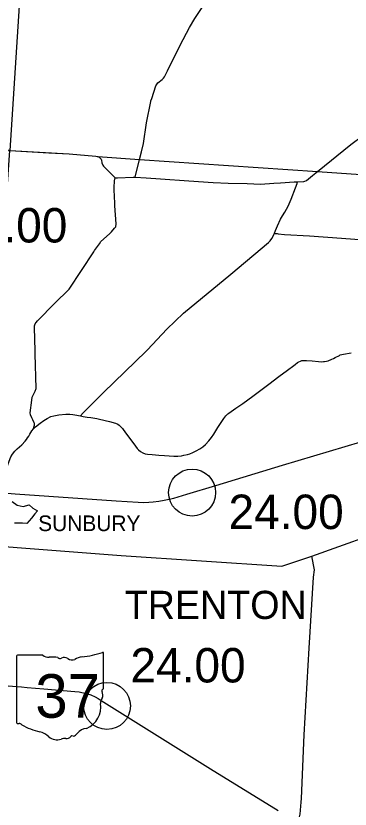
# Model space of a CAD drawing. Extents: x 1597222 to 1925846, y 496284 to 911751.
# Drawn here: x 1872161 to 1882846, y 810051 to 835395 of the extents above; entities that cross this region are included whole.
import ezdxf

# ---------------------------------------------------------------- set-up
doc = ezdxf.new("R2010")
doc.units = 0
for name, color, linetype in [('Default', 7, 'Continuous'), ('GM_X_Corporation', 7, 'Continuous'), ('GM_X_Corporation_Text', 7, 'Continuous'), ('GM_X_County_Road', 7, 'Continuous'), ('GM_X_State_Route', 7, 'Continuous'), ('GM_X_State_Shield', 7, 'Continuous'), ('GM_X_Township', 7, 'Continuous'), ('GM_X_Township_Road', 7, 'Continuous'), ('GM_X_Township_Text', 7, 'Continuous'), ('GM_X_US_Route', 7, 'Continuous')]:
    doc.layers.add(name, color=color, linetype=linetype)

msp = doc.modelspace()

# ---------------------------------------------------------------- linework, layer by layer
at = {"layer": 'Default'}
for centre in [(1877795, 820165), (1875074, 813348)]:
    msp.add_circle(centre, 750, dxfattribs=at)
at = {"layer": 'GM_X_Corporation'}
msp.add_lwpolyline([(1872043, 819876), (1872199, 819766), (1872392, 819723), (1872582, 819770), (1872706, 819663), (1872848, 819582), (1872764, 819484), (1872661, 819350), (1872513, 819172), (1872369, 819183), (1872118, 819190)], dxfattribs=at)
at = {"layer": 'GM_X_County_Road'}
for points in [[(1881648, 830290), (1881808, 830417), (1882869, 831288), (1883240, 831567)], [(1874227, 822615), (1874317, 822710), (1874959, 823358), (1876327, 824682), (1876365, 824720), (1876987, 825381), (1877524, 825893), (1879029, 827144), (1880240, 828159), (1880290, 828209), (1880342, 828279), (1880387, 828358), (1880432, 828452), (1880464, 828542), (1880520, 828684), (1880625, 828898), (1880689, 829004), (1880756, 829118), (1880864, 829316), (1880962, 829539), (1881103, 829903), (1881150, 830037), (1881159, 830094), (1881361, 830106), (1881400, 830115), (1881455, 830137), (1881648, 830290)], [(1872724, 822198), (1872792, 822267), (1872943, 822383), (1873056, 822467), (1873160, 822533), (1873276, 822590), (1873373, 822621), (1873532, 822646), (1873759, 822667), (1873891, 822665), (1873977, 822657), (1874044, 822647), (1874227, 822615), (1874315, 822599), (1874444, 822579), (1874557, 822560), (1874752, 822527), (1874836, 822512), (1875152, 822435), (1875346, 822380), (1875416, 822349), (1875458, 822321), (1875497, 822287), (1875565, 822207), (1875667, 822073), (1875831, 821849), (1875981, 821648), (1876039, 821575), (1876079, 821533), (1876143, 821482), (1876217, 821438), (1876297, 821406), (1876374, 821389), (1876519, 821376), (1876727, 821364), (1876913, 821349), (1877214, 821328), (1877336, 821330), (1877454, 821342), (1877534, 821356), (1877649, 821382), (1877722, 821406), (1877821, 821445), (1877928, 821496), (1878043, 821558), (1878138, 821626), (1878219, 821701), (1878331, 821818), (1878413, 821920), (1878486, 822032), (1878616, 822239), (1878743, 822436), (1878811, 822535), (1878842, 822578), (1878871, 822613), (1878895, 822642), (1878934, 822678), (1878967, 822704), (1879044, 822758), (1879197, 822860), (1879414, 823008), (1879735, 823245), (1879901, 823370), (1880245, 823625), (1880570, 823871), (1880847, 824079), (1881042, 824227), (1881087, 824259), (1881166, 824319), (1881210, 824345), (1881256, 824365), (1881305, 824380), (1881378, 824389), (1881448, 824388), (1881628, 824373), (1881838, 824352), (1881925, 824346), (1881993, 824349), (1882027, 824352), (1882091, 824364), (1882142, 824378), (1882259, 824424), (1882312, 824450), (1882368, 824481), (1882502, 824549), (1882531, 824563), (1882576, 824578), (1882637, 824590), (1882881, 824632)], [(1871742, 820151), (1871742, 820151), (1871754, 820333), (1871771, 820532), (1871780, 820600), (1871796, 820672), (1871893, 821017), (1871942, 821170), (1871996, 821311), (1872051, 821390), (1872132, 821486), (1872206, 821558), (1872281, 821630), (1872352, 821694), (1872457, 821804), (1872502, 821861), (1872537, 821910), (1872571, 821965), (1872610, 822031), (1872673, 822132), (1872724, 822198)], [(1871277, 818480), (1872206, 818406), (1875525, 818156), (1880663, 817814), (1881619, 818131), (1884362, 819111), (1887858, 818871), (1889457, 818761), (1891623, 818604), (1892346, 818560), (1895326, 818344), (1897532, 818224), (1897769, 818211), (1897801, 818204), (1897822, 818179)]]:
    msp.add_lwpolyline(points, dxfattribs=at)
at = {"layer": 'GM_X_State_Route'}
msp.add_lwpolyline([(1871455, 814026), (1871491, 814021), (1871569, 814014), (1871759, 814000), (1871910, 813989), (1872340, 813955), (1872527, 813939), (1873053, 813896), (1874044, 813812), (1874182, 813797), (1874274, 813782), (1874381, 813759), (1874562, 813699), (1874700, 813634), (1874793, 813581), (1874892, 813523), (1878383, 811338), (1880549, 810005)], dxfattribs=at)
at = {"layer": 'GM_X_State_Shield'}
for p, q in [((1872182, 814935), (1872182, 812822)), ((1872182, 814935), (1872182, 812822)), ((1873024, 814972), (1872209, 814972)), ((1873024, 814972), (1872209, 814972)), ((1874966, 813919), (1874966, 815024)), ((1874966, 813919), (1874966, 815024)), ((1874966, 813919), (1874966, 813919)), ((1874966, 813919), (1874966, 813919))]:
    msp.add_line(p, q, dxfattribs=at)
for centre, radius, start, end in [((1873974, 817853), 2953, 275.8445, 288.9065), ((1873974, 817853), 2953, 275.8445, 288.9065), ((1874935, 815029), 31, 351.8621, 97.738), ((1874935, 815029), 31, 351.8621, 97.738), ((1872213, 814940), 32.3, 98.1301, 188.1301), ((1872213, 814940), 32.3, 98.1301, 188.1301), ((1873219, 815217), 313, 231.6195, 271.1119), ((1873219, 815217), 313, 231.6195, 271.1119), ((1873322, 813785), 1123, 80.4867, 94.9883), ((1873322, 813785), 1123, 80.4867, 94.9883), ((1873577, 814951), 90.3, 219.7921, 297.1024), ((1873577, 814951), 90.3, 219.7921, 297.1024), ((1873710, 814707), 188, 54.4667, 119.1411), ((1873710, 814707), 188, 54.4667, 119.1411), ((1873952, 815042), 226, 233.8562, 294.8282), ((1873952, 815042), 226, 233.8562, 294.8282), ((1874351, 814326), 594, 97.3462, 120.7689), ((1874351, 814326), 594, 97.3462, 120.7689), ((1874959, 813838), 48, 107.944, 210.337), ((1874959, 813838), 48, 107.944, 210.337), ((1874654, 813698), 288, 340.033, 23.6496), ((1874654, 813698), 288, 340.033, 23.6496), ((1874933, 813914), 33.2, 289.6038, 7.7341), ((1874933, 813914), 33.2, 289.6038, 7.7341), ((1875077, 813456), 210, 136.8065, 186.9296), ((1875077, 813456), 210, 136.8065, 186.9296), ((1874139, 813315), 739, 292.3089, 8.9858), ((1874139, 813315), 739, 292.3089, 8.9858), ((1872214, 812818), 32.5, 171.9584, 258.3066), ((1872214, 812818), 32.5, 171.9584, 258.3066), ((1872219, 813034), 248, 267.339, 280.6039), ((1872219, 813034), 248, 267.339, 280.6039), ((1872269, 812700), 89.5, 29.7484, 93.2717), ((1872269, 812700), 89.5, 29.7484, 93.2717), ((1873400, 814599), 2132, 240.4129, 257.1985), ((1873400, 814599), 2132, 240.4129, 257.1985), ((1872764, 811873), 667, 47.1842, 75.836), ((1872764, 811873), 667, 47.1842, 75.836), ((1874451, 812229), 404, 94.4031, 142.5768), ((1874451, 812229), 404, 94.4031, 142.5768), ((1873486, 812690), 423, 230.7004, 286.2918), ((1873486, 812690), 423, 230.7004, 286.2918), ((1873731, 811959), 348, 85.6951, 111.2099), ((1873731, 811959), 348, 85.6951, 111.2099), ((1873761, 812531), 226, 268.777, 315.5493), ((1873761, 812531), 226, 268.777, 315.5493), ((1873965, 812327), 63.5, 65.7517, 132.6484), ((1873965, 812327), 63.5, 65.7517, 132.6484), ((1873938, 812617), 239, 282.8732, 323.2771), ((1873938, 812617), 239, 282.8732, 323.2771)]:
    msp.add_arc(centre, radius, start, end, dxfattribs=at)
at = {"layer": 'GM_X_Township'}
for points in [[(1850615, 859080), (1861827, 858324), (1863977, 858188), (1869100, 857855), (1873671, 857558), (1873447, 853777), (1873266, 851105), (1872889, 845433), (1872874, 845201), (1872678, 842151), (1872497, 839344), (1872306, 836385), (1871965, 831096), (1871301, 831135), (1870943, 831158), (1868637, 831266), (1861106, 831707), (1859467, 831803), (1858606, 831851), (1854821, 832136)], [(1870309, 808163), (1870779, 814239), (1870903, 816053), (1870933, 816495), (1870943, 816996), (1871003, 817857), (1871065, 818497), (1871124, 819057), (1871199, 820179), (1871965, 831096), (1873866, 830983), (1874715, 830911), (1874782, 830900), (1876113, 830808), (1881808, 830417), (1885186, 830186), (1888609, 830001), (1895732, 829600), (1898513, 829466)]]:
    msp.add_lwpolyline(points, dxfattribs=at)
at = {"layer": 'GM_X_Township_Road'}
for points in [[(1876176, 831049), (1876244, 831313), (1876339, 831976), (1876476, 832658), (1876479, 832675), (1876506, 832758), (1876634, 833154), (1876703, 833255), (1876835, 833358), (1876875, 833401), (1876911, 833448), (1876937, 833491), (1877010, 833643), (1877414, 834454), (1877715, 835018), (1877883, 835308), (1878069, 835602), (1878276, 835912), (1878286, 835945), (1878286, 835969), (1878279, 835990)], [(1871925, 831098), (1871965, 831096), (1873217, 831021)], [(1873217, 831021), (1873866, 830982), (1874715, 830911), (1874765, 830902)], [(1875972, 830241), (1876113, 830808), (1876176, 831049)], [(1874765, 830902), (1874783, 830900), (1874828, 830878), (1874871, 830836), (1874883, 830819), (1874897, 830780), (1874913, 830695), (1874941, 830628), (1874964, 830595), (1875107, 830442), (1875306, 830250), (1875338, 830221), (1875351, 830222)], [(1872724, 822198), (1872740, 822251), (1872755, 822319), (1872752, 822371), (1872746, 822394), (1872704, 822488), (1872669, 822549), (1872625, 822647), (1872615, 822712), (1872668, 823117), (1872687, 823211), (1872776, 823402), (1872815, 823486), (1872782, 824594), (1872778, 824698), (1872760, 825437), (1872758, 825496), (1872774, 825554), (1872808, 825595), (1872850, 825648), (1873403, 826215), (1873458, 826272), (1873801, 826601), (1873865, 826663), (1874648, 827854), (1874679, 827899), (1874830, 828116), (1874879, 828186), (1875151, 828436), (1875213, 828493), (1875315, 828614), (1875353, 828659), (1875371, 828749), (1875327, 829329), (1875320, 829415), (1875305, 829837), (1875302, 829912), (1875309, 830123), (1875338, 830221)], [(1875351, 830222), (1875410, 830224), (1875906, 830241), (1875972, 830241)], [(1875972, 830241), (1876325, 830221), (1876782, 830190), (1877695, 830124), (1878463, 830066), (1878952, 830045), (1879551, 830034), (1879982, 830022), (1880411, 830048), (1880624, 830061), (1881052, 830089), (1881159, 830094)], [(1880432, 828452), (1880452, 828445), (1880516, 828438), (1880549, 828431), (1880745, 828411), (1881545, 828362), (1882567, 828296), (1884124, 828178)], [(1881144, 809643), (1881165, 809679), (1881231, 809806), (1881247, 809894), (1881278, 810269), (1881288, 810392), (1881379, 812426), (1881535, 815194), (1881680, 817467), (1881704, 817701), (1881619, 818131)]]:
    msp.add_lwpolyline(points, dxfattribs=at)
at = {"layer": 'GM_X_US_Route'}
msp.add_lwpolyline([(1871153, 820180), (1871199, 820179), (1871742, 820151), (1872137, 820124), (1875367, 819897), (1876072, 819853), (1876232, 819852), (1876406, 819857), (1876545, 819867), (1876727, 819890), (1876899, 819917), (1877009, 819941), (1877209, 819989), (1877624, 820113), (1878554, 820394), (1880687, 821035), (1883192, 821790)], dxfattribs=at)

# ---------------------------------------------------------------- texts
at = {"layer": 'Default'}
for s, p in [('2.00', (1870944, 828154)), ('24.00', (1878959, 818999)), ('24.00', (1875824, 814098))]:
    msp.add_text(s, height=1100, dxfattribs=at).set_placement(p)
at = {"layer": 'GM_X_Corporation_Text'}
msp.add_text('SUNBURY', height=500, rotation=0, dxfattribs=at).set_placement((1872874, 818933))
at = {"layer": 'GM_X_State_Shield'}
msp.add_text('37', height=1392.2, dxfattribs=at).set_placement((1872782, 812971))
msp.add_text('37', height=1392.2, dxfattribs=at).set_placement((1872782, 812971))
at = {"layer": 'GM_X_Township_Text'}
msp.add_text('TRENTON', height=900, rotation=0, dxfattribs=at).set_placement((1875642, 816126))

doc.saveas('drawing.dxf')
